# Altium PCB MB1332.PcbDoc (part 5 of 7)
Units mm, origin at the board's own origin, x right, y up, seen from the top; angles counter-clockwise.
Board outline 161 x 75 mm, 6 copper layers (Top Layer, Signal Layer 1, Signal Layer 2, Signal Layer 3, Signal Layer 4, Bottom Layer), stack 1.57 mm thick; 387 components, 358 nets, 1659 pads, 1180 vias.
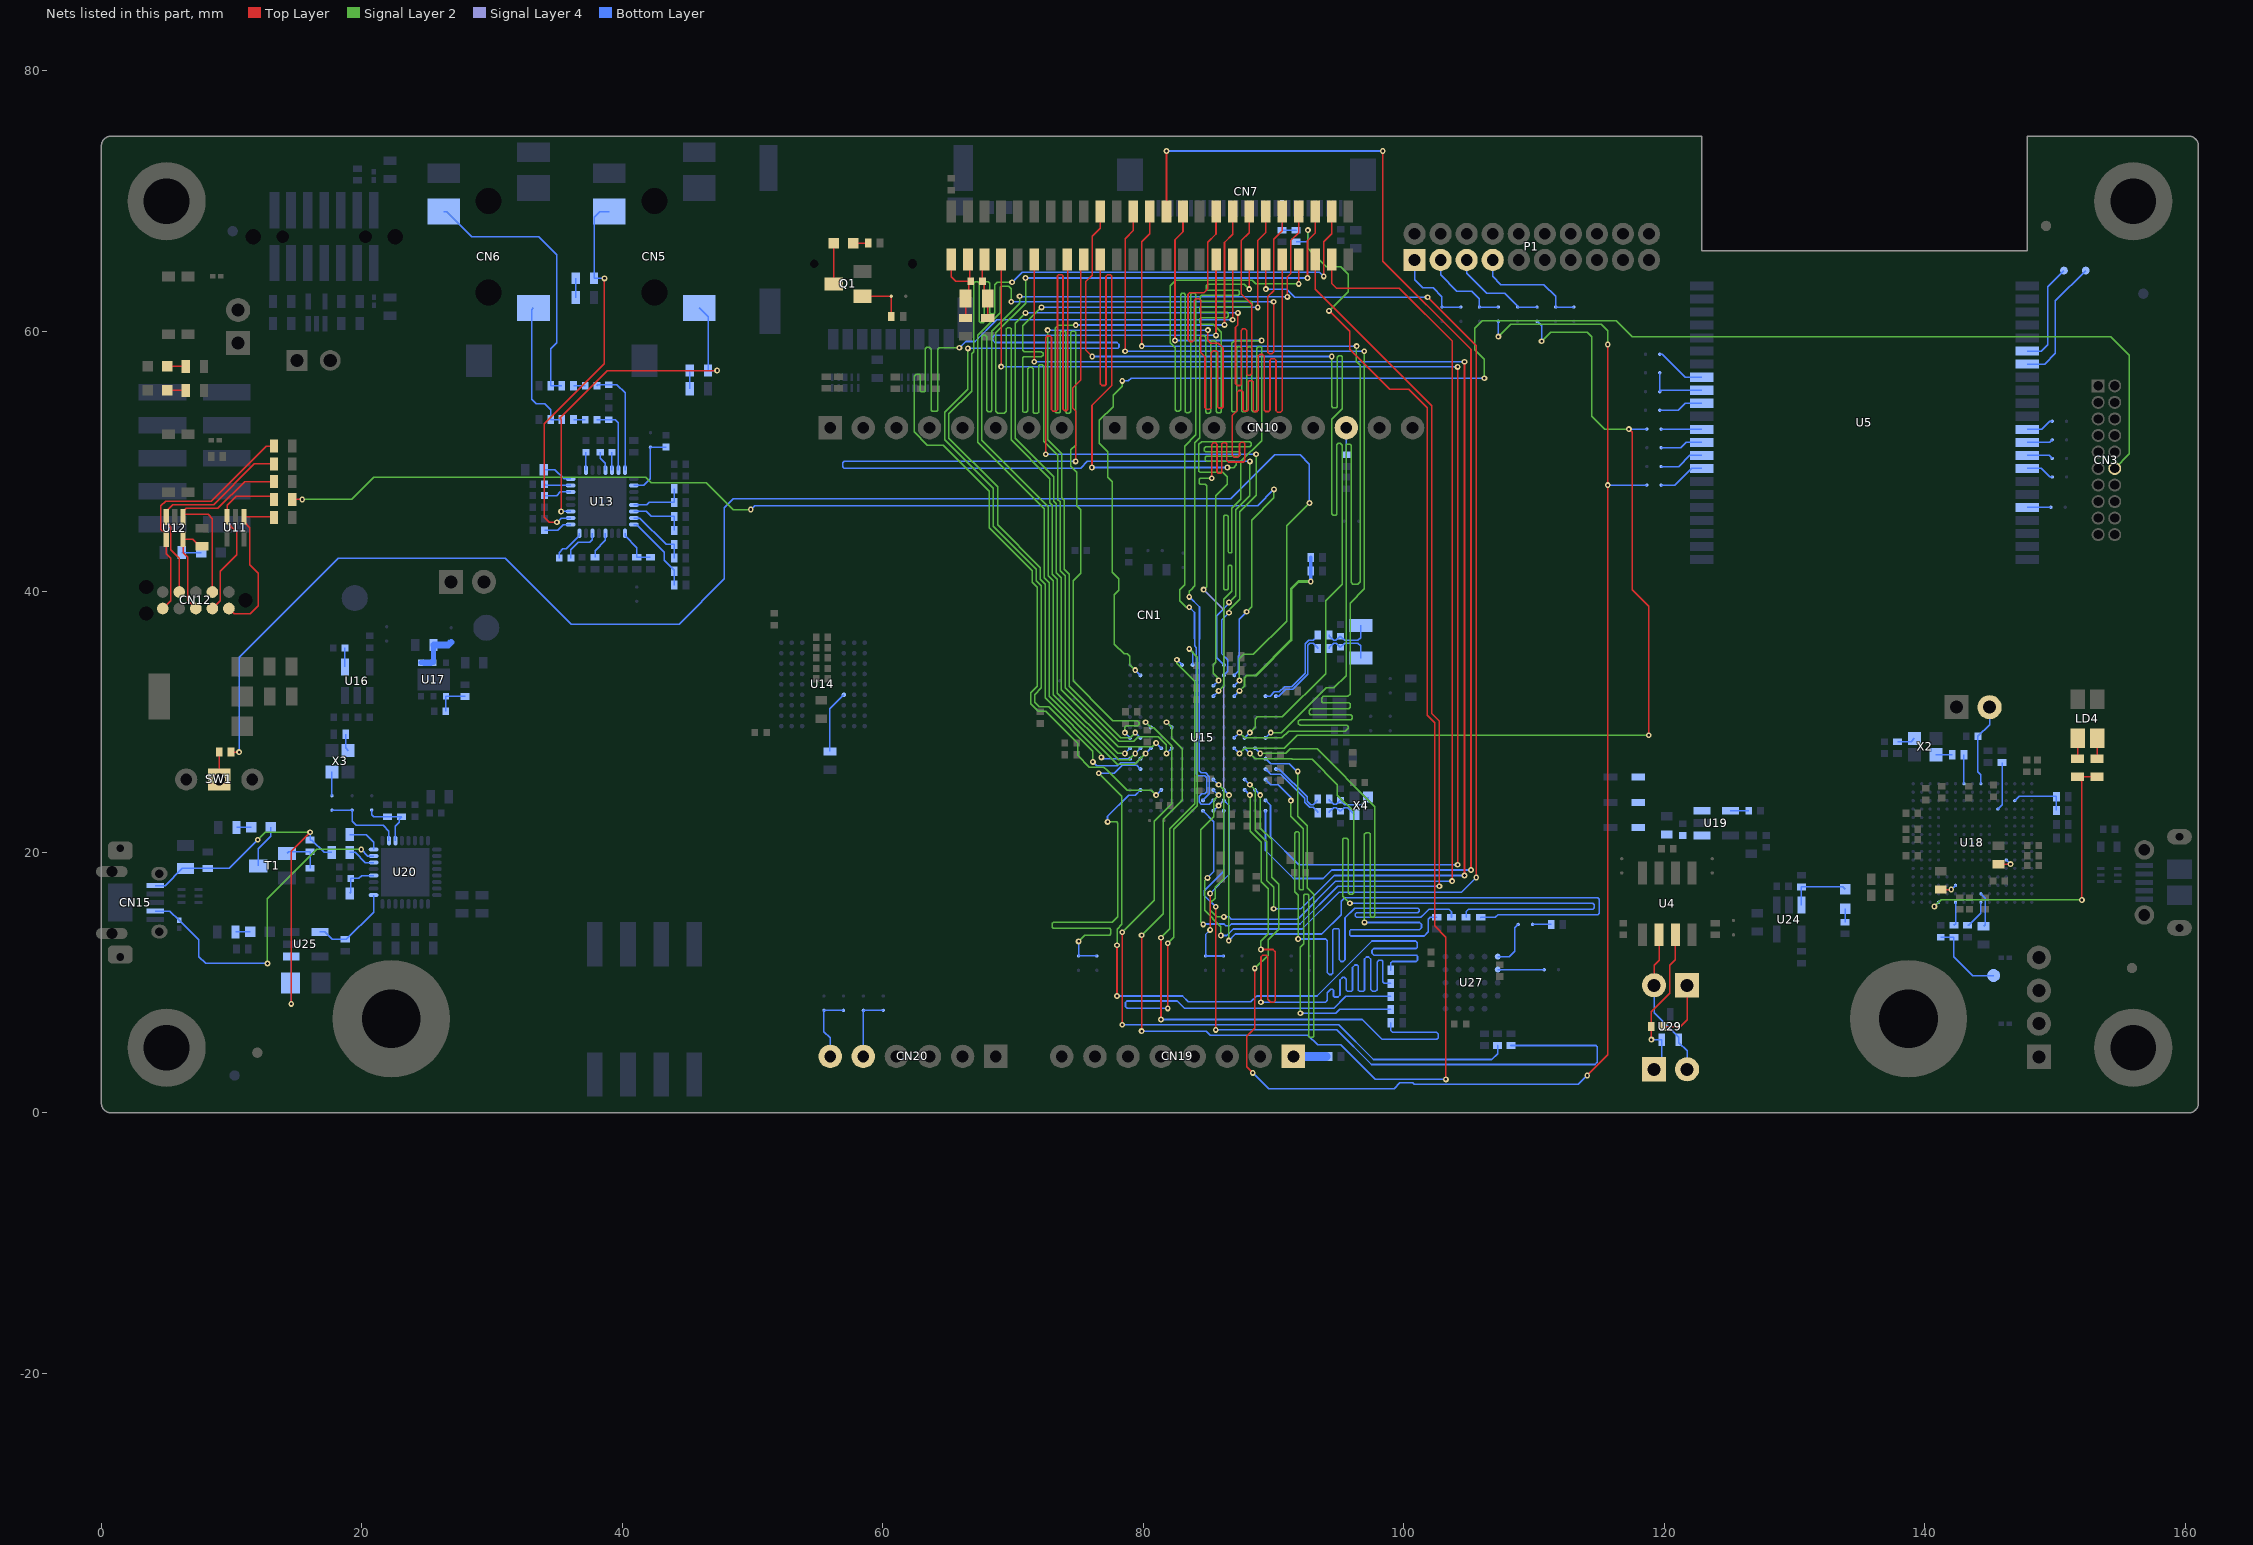
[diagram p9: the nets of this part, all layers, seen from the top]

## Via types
v1: diameter 0.45, hole 0.2, Top Layer to Bottom Layer, tented both sides, 1180 vias

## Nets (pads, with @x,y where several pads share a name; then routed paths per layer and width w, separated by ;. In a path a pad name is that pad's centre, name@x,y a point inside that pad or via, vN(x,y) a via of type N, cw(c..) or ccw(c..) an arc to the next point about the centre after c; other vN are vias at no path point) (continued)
LCD_B5: CN1.31 U15.C7 | length 83.5
  Top Layer w0.127: v1(76.05,49.55) 76.05,54.325 77.579,55.854 77.579,64.246 77.475,64.35 77.25,64.35 77.125,64.225 77.125,55.925 77.05,55.85 76.815,55.85 76.69,55.975 CN1.31@76.69,65.531
  Signal Layer 2 w0.102: v1(85.775,33.198) 85.775,33.348 85.375,33.748 85.375,34.423 85.563,34.611 85.563,47.388 86.45,48.275 86.45,48.825 86.1,49.175 84.357,49.175 84.257,49.275 84.257,51.324 84.482,51.549 88.151,51.549 88.271,51.429 88.271,51.254 88.167,51.15 84.775,51.15 84.675,51.05 84.675,50.85 84.775,50.75 87.375,50.75 87.45,50.675 87.45,50.525 87.325,50.4 84.825,50.4 84.75,50.325 84.75,50.125 84.85,50.025 87,50.025 87.125,49.9 87.125,49.75 86.925,49.55 v1(86.45,49.55)
  Bottom Layer w0.1: U15.C7@85.375,32.798 v1(85.775,33.198)
  Bottom Layer w0.127: v1(76.05,49.55) v1(86.45,49.55)
LCD_B6: CN1.33 U15.A6 | length 82.6
  Top Layer w0.127: v1(74.8,50.025) 74.8,52.152 74.804,52.156 74.804,53.896 74.575,54.125 74.575,55.65 75.2,56.275 75.2,65.312 CN1.33@75.42,65.531
  Signal Layer 2 w0.102: v1(86.575,39.198) 87.094,39.717 87.094,46.296 88.175,47.377 v1(88.175,50.025)
  Bottom Layer w0.127: v1(74.8,50.025) 57.025,50.025 56.925,49.925 56.925,49.6 57.019,49.506 75.181,49.506 75.7,50.025 v1(88.175,50.025) ; U15.A6@86.175,34.398 85.622,34.951 85.622,38.18 86.575,39.133 v1(86.575,39.198)
LCD_B7: CN1.35 U15.B6 | length 83.1
  Top Layer w0.127: v1(72.5,50.575) 72.5,59.55 72.6,59.65 72.85,59.65 72.95,59.55 72.95,54 73.075,53.875 73.275,53.875 73.4,54 73.4,64.25 73.5,64.35 73.725,64.35 73.825,64.25 73.825,54.025 73.925,53.925 74.119,53.925 74.194,54 74.194,65.487 CN1.35@74.15,65.531
  Signal Layer 2 w0.102: v1(86.575,38.398) 86.575,38.623 87.4,39.448 87.4,46.169 88.65,47.419 v1(88.65,50.575)
  Bottom Layer w0.1: U15.B6@86.175,33.598 86.475,33.898 86.475,34.798
  Bottom Layer w0.127: v1(72.5,50.575) v1(88.65,50.575) ; 86.475,34.798 86.003,35.27 86.003,37.826 v1(86.575,38.398)
LCD_BL_CTRL: CN1.43 U15.P2 | length 99.7
  Top Layer w0.127: CN1.43@69.07,65.531 69.075,65.526 v1(69.075,57.3) ; v1(104.125,19.05) v1(104.125,57.275)
  Bottom Layer w0.127: v1(69.075,57.3) 69.094,57.281 104.119,57.281 v1(104.125,57.275) ; U15.P2@89.375,23.998 89.756,23.617 89.756,21.219 91.925,19.05 v1(104.125,19.05)
LCD_CLK: CN1.32 U15.H4 | length 84.1
  Top Layer w0.127: v1(76.075,58.075) 75.581,58.569 75.581,63.83 76.075,64.324 76.075,67.3 76.69,67.915 CN1.32@76.69,69.217
  Signal Layer 2 w0.102: v1(88.175,29.198) 88.575,29.598 88.575,30.223 88.75,30.398 90.675,30.398 94.005,33.728 94.005,39.331 95.251,40.577 95.251,41.754 95.25,41.755 95.25,51.275 95.125,51.4 94.95,51.4 94.85,51.3 94.85,45.975 94.775,45.9 94.575,45.9 94.456,46.019 94.456,53.256 95.25,54.05 95.25,58.075 95.175,58.15 95,58.15 94.875,58.025 94.875,54.225 94.8,54.15 94.556,54.15 94.456,54.25 v1(94.456,58.075)
  Bottom Layer w0.127: v1(76.075,58.075) v1(94.456,58.075) ; U15.H4@87.775,28.798 v1(88.175,29.198)
LCD_DE: CN1.22 U15.D7 | length 89.7
  Top Layer w0.127: v1(82.425,59.3) 82.425,67.05 83.04,67.665 CN1.22@83.04,69.217
  Signal Layer 2 w0.1: 86.175,39.304 86.175,39.45 86.573,39.848
  Signal Layer 2 w0.102: v1(85.775,32.398) 86.175,32.798 86.175,39.304 ; 86.573,39.848 86.788,40.063 86.788,41.987 86.725,42.05 86.575,42.05 86.5,41.975 86.5,40.25 86.425,40.175 86.25,40.175 86.175,40.25 86.175,45.809 86.25,45.885 86.415,45.885 86.5,45.8 86.5,43.075 86.55,43.025 86.75,43.025 86.788,43.063 86.788,46.422 87.475,47.11 87.475,50.025 89.075,51.625 89.075,58.75 89,58.825 88.8,58.825 88.7,58.725 88.7,53.95 88.6,53.85 88.425,53.85 88.325,53.95 88.325,58.725 88.225,58.825 88.05,58.825 87.925,58.7 87.925,53.95 87.825,53.85 87.625,53.85 87.55,53.925 87.55,58.725 87.45,58.825 87.25,58.825 87.175,58.75 87.175,53.925 87.1,53.85 86.875,53.85 86.8,53.925 86.8,59.075 87.025,59.3 v1(89.075,59.3)
  Bottom Layer w0.127: v1(82.425,59.3) v1(89.075,59.3) ; U15.D7@85.375,31.998 v1(85.775,32.398)
LCD_G0: CN1.4 U15.K15 | length 87.5
  Top Layer w0.127: v1(93.85,64.225) 93.85,66.875 94.47,67.495 CN1.4@94.47,69.217
  Signal Layer 2 w0.102: v1(69.925,63.775) 68.775,63.775 68.571,63.571 68.571,61.429 68.517,61.375 68.275,61.375 68.2,61.45 68.2,63.7 68.1,63.8 67.9,63.8 67.8,63.7 67.8,60.775 67.7,60.675 67.5,60.675 67.4,60.775 67.4,63.7 67.3,63.8 67.075,63.8 66.977,63.702 66.977,58.452 66.825,58.3 66.825,55.425 65.069,53.669 65.069,51.806 68.8,48.075 68.8,45.15 72.082,41.868 72.082,40.98 72.467,40.596 72.467,31.858 76.775,27.55 v1(76.775,27.298)
  Bottom Layer w0.1: v1(76.775,27.298) 76.875,27.198 U15.K15@78.975,27.198
  Bottom Layer w0.127: v1(69.925,63.775) 70.7,64.55 93.525,64.55 v1(93.85,64.225)
LCD_G1: CN1.6 U15.J15 | length 83
  Top Layer w0.127: v1(92.6,64.1) 92.6,66.95 93.2,67.55 CN1.6@93.2,69.217
  Signal Layer 2 w0.102: v1(70.95,64.1) 70.95,62.167 68.675,59.892 68.675,53.875 68.825,53.725 69.325,53.725 69.475,53.875 69.475,60.2 69.575,60.3 69.75,60.3 69.843,60.207 69.843,51.676 72.821,48.698 72.821,46.837 73,46.658 73,41.361 73.385,40.976 73.385,32.238 78.025,27.598 v1(78.575,27.598)
  Bottom Layer w0.127: v1(70.95,64.1) v1(92.6,64.1) ; v1(78.575,27.598) U15.J15@78.975,27.998
LCD_G2: CN1.8 U15.J14 | length 82.6
  Top Layer w0.127: v1(91.05,62.65) 91.05,64.175 91.3,64.425 91.3,66.95 91.93,67.58 CN1.8@91.93,69.217
  Signal Layer 2 w0.102: v1(70.5,62.7) 70.5,62.15 68.369,60.019 68.369,53.944 68.275,53.85 68.075,53.85 67.975,53.95 67.975,59.6 67.95,59.625 67.875,59.7 67.708,59.7 67.589,59.581 67.589,51.636 72.694,46.531 72.694,41.234 73.079,40.849 73.079,32.112 78.092,27.098 78.875,27.098 v1(79.375,27.598)
  Bottom Layer w0.127: v1(70.5,62.7) 70.536,62.664 91.036,62.664 v1(91.05,62.65) ; v1(79.375,27.598) U15.J14@79.775,27.998
LCD_G3: CN1.10 U15.J13 | length 82.7
  Top Layer w0.127: v1(90,62.275) 90,58.414 89.861,58.275 89.675,58.275 89.55,58.4 89.55,62.675 90,63.125 90,67.075 90.66,67.735 CN1.10@90.66,69.217
  Signal Layer 2 w0.102: v1(69.85,62.275) 69.85,63.275 69.656,63.469 69.075,63.469 69,63.394 69,61.425 67.283,59.708 67.283,51.509 72.388,46.404 72.388,41.107 72.773,40.722 72.773,31.985 77.984,26.773 79.35,26.773 v1(80.175,27.598)
  Bottom Layer w0.127: v1(69.85,62.275) v1(90,62.275) ; v1(80.175,27.598) U15.J13@80.575,27.998
LCD_G4: CN1.12 U15.J11 | length 84.2
  Top Layer w0.127: v1(88.775,61.85) 88.775,66.975 89.39,67.59 CN1.12@89.39,69.217
  Signal Layer 2 w0.102: v1(72.175,61.85) 70.75,60.425 70.75,58.55 70.85,58.45 72.175,58.45 72.3,58.325 72.3,58.175 72.176,58.051 70.826,58.051 70.75,57.975 70.75,53.85 70.8,53.8 71.025,53.8 71.125,53.9 71.125,57.15 71.225,57.25 71.425,57.25 71.525,57.15 71.525,53.8 71.625,53.7 71.85,53.7 71.95,53.8 71.95,57.375 72.025,57.45 72.225,57.45 72.344,57.331 72.344,51.573 73.433,50.484 73.433,47.09 73.612,46.911 73.612,41.614 73.997,41.229 73.997,32.644 78.092,28.548 79.257,28.548 79.606,28.898 81.127,28.898 81.768,28.257 81.768,27.605 v1(81.775,27.598)
  Bottom Layer w0.127: v1(72.175,61.85) v1(88.775,61.85) ; v1(81.775,27.598) U15.J11@82.175,27.998
LCD_G5: CN1.14 U15.J12 | length 84.4
  Top Layer w0.127: v1@87.25,61.4 87.25,60.5 87.075,60.325 87.075,55.975 87.2,55.85 87.436,55.85 87.525,55.939 87.525,60.1 87.625,60.2 87.8,60.2 87.925,60.075 87.925,56.725 88.025,56.625 88.211,56.625 88.325,56.739 88.325,62.075 87.5,62.9 87.5,66.95 88.12,67.57 CN1.14@88.12,69.217
  Signal Layer 2 w0.102: v1(70.95,61.425) 70.149,60.624 70.149,51.803 73.127,48.825 73.127,46.964 73.306,46.784 73.306,41.487 73.691,41.103 73.691,32.482 78.075,28.098 80.675,28.098 v1(80.975,28.398)
  Bottom Layer w0.127: v1(70.95,61.425) v1(87.25,61.425) ; v1(80.975,28.398) U15.J12@81.375,27.998
LCD_G6: CN1.16 U15.H15 | length 84.9
  Top Layer w0.127: v1(86.225,60.5) 86.225,66.825 86.85,67.45 CN1.16@86.85,69.217
  Signal Layer 2 w0.1: 77.225,30.55 77.65,30.125 79.525,30.125 79.675,29.975 79.675,29.825 79.575,29.725 78.675,29.725 78.575,29.625 v1(78.575,29.198)
  Signal Layer 2 w0.102: v1(74.808,60.488) 74.8,60.481 74.8,60.475 73.475,60.475 73.225,60.225 73.225,53.85 73.325,53.75 73.525,53.75 73.625,53.85 73.625,59.95 73.7,60.025 73.95,60.025 74.025,59.95 74.025,53.825 74.125,53.725 74.3,53.725 74.425,53.85 74.425,59.925 74.525,60.025 74.7,60.025 74.8,59.925 74.8,51.275 74.422,50.897 74.422,49.653 74.9,49.175 74.9,46.6 75.2,46.3 75.2,41.433 74.609,40.842 74.609,33.164 77.224,30.549
  Bottom Layer w0.127: v1(74.808,60.488) 86.213,60.488 v1(86.225,60.5) ; v1(78.575,29.198) U15.H15@78.975,28.798
LCD_G7: CN1.18 U15.H14 | length 88.5
  Top Layer w0.127: v1(84.95,60.1) 84.95,59.313 85.162,59.1 85.75,59.1 86.107,58.743 86.107,54.2 86.031,54.125 85.775,54.125 85.7,54.2 85.7,58.4 85.575,58.525 85.35,58.525 85.2,58.375 85.2,54.15 85.075,54.025 84.85,54.025 84.731,54.144 84.731,58.058 84.4,58.389 84.4,62.375 84.275,62.5 84.025,62.5 83.9,62.375 83.9,59.35 83.775,59.225 83.564,59.225 83.421,59.368 83.421,62.85 83.546,62.975 84.65,62.975 84.95,63.275 84.95,66.85 85.58,67.48 CN1.18@85.58,69.217
  Signal Layer 2 w0.102: v1(72.65,60.1) 72.65,51.7 73.739,50.611 73.739,47.217 73.918,47.038 73.918,41.741 74.303,41.356 74.303,32.77 78.251,28.822 78.999,28.822 v1(79.375,29.198)
  Bottom Layer w0.127: v1(72.65,60.1) v1(84.95,60.1) ; v1(79.375,29.198) U15.H14@79.775,28.798
LCD_HSYNC: CN1.26 U15.H2 | length 83
  Top Layer w0.127: v1(79.875,58.875) 79.875,66.875 80.5,67.5 CN1.26@80.5,69.217
  Signal Layer 2 w0.102: v1(89.775,29.198) 90.6,29.198 94.05,32.648 94.625,32.648 95.557,33.58 95.557,41.882 95.556,41.883 95.556,51.281 95.625,51.35 95.85,51.35 95.95,51.25 95.95,40.725 96.075,40.6 96.45,40.6 96.65,40.8 96.65,57.4 96.35,57.7 96.35,58.85 v1(96.375,58.875)
  Bottom Layer w0.127: v1(79.875,58.875) v1(96.375,58.875) ; U15.H2@89.375,28.798 v1(89.775,29.198)
LCD_INT: CN1.39 U15.M4 | length 106.9
  Top Layer w0.127: CN1.39@71.61,65.531 71.625,65.516 v1(71.625,57.675) ; v1(104.65,18.225) v1(104.65,57.675)
  Signal Layer 2 w0.127: v1(88.175,25.198) 88.586,24.787 88.586,21.712 89.475,20.823 89.475,17.85 90,17.325 v1(90,15.675)
  Bottom Layer w0.127: v1(71.625,57.675) 71.631,57.681 71.637,57.675 v1(104.65,57.675) ; U15.M4@87.775,25.598 v1(88.175,25.198) ; v1(90,15.675) 92.1,15.675 94.65,18.225 v1(104.65,18.225)
LCD_ON/OFF: CN1.24 U15.R2 | length 99.2
  Top Layer w0.127: CN1.24@81.77,69.217 81.775,69.222 v1(81.775,73.85) ; v1(98.375,73.85) 98.375,65.4 105.15,58.625 v1(105.15,18.65)
  Bottom Layer w0.127: v1(81.775,73.85) v1(98.375,73.85) ; U15.R2@89.375,23.198 89.375,20.15 91.525,18 93.8,18 94.45,18.65 v1(105.15,18.65)
LCD_R0: CN1.3 U15.M7 | length 85.3
  Top Layer w0.127: CN1.3@94.47,65.531 94.47,63.68 94.825,63.325 99.65,63.325 103.7,59.275 v1(103.7,17.8) v1@103.7,17.725
  Signal Layer 2 w0.1: 86.175,20.623 86.175,24.015
  Signal Layer 2 w0.102: v1(85.775,25.198) 86.175,24.798 86.175,24.015 ; v1(86.175,15.05) 85.65,15.05 85.15,15.55 85.15,16.125 85.525,16.5 85.525,17.325 86.175,17.975 86.175,20.623
  Bottom Layer w0.127: U15.M7@85.375,25.598 v1(85.775,25.198) ; v1(86.175,15.05) 86.575,15.05 86.743,14.882 91.857,14.882 94.775,17.8 v1(103.7,17.8)
LCD_R1: CN1.5 U15.N7 | length 83.2
  Top Layer w0.127: CN1.5@93.2,65.531 93.2,63.25 102.151,54.299 ; 101.8,54.65 102.151,54.299 ; v1(102.725,17.4) 102.725,30.095 102.151,30.669 102.151,54.299
  Signal Layer 2 w0.102: v1(84.6,14.473) 84.398,14.675 84.398,21.74 85.399,22.741 85.399,24.022 v1(85.775,24.398)
  Bottom Layer w0.127: v1(84.6,14.473) 84.628,14.501 86.186,14.501 86.317,14.369 86.616,14.369 86.748,14.501 92.026,14.501 94.925,17.4 v1(102.725,17.4) ; U15.N7@85.375,24.798 v1(85.775,24.398)
LCD_R2: CN1.7 U15.P7 | length 92.9
  Top Layer w0.127: v1(91.925,63.65) CN1.7@91.93,65.531
  Signal Layer 2 w0.1: 83.177,40.983 83.177,40.551 82.795,40.169 82.795,39.328 83.3,38.823
  Signal Layer 2 w0.102: 83.177,40.983 83.177,51.202 84.025,52.05 84.025,62.85 83.925,62.95 83.725,62.95 83.625,62.85 83.625,53.875 83.5,53.75 83.325,53.75 83.225,53.85 83.225,62.825 83.125,62.925 82.95,62.925 82.85,62.825 82.85,54 82.725,53.875 82.55,53.875 82.436,53.989 82.436,58.757 82.049,59.144 82.049,63.499 82.475,63.925 88.35,63.925 88.625,63.65 v1(91.925,63.65) ; 83.3,38.823 v1(83.525,38.823)
  Bottom Layer w0.1: 83.925,36.402 83.925,35.873 84.075,35.723 84.075,26.048 84.225,25.898 84.699,25.898 84.875,25.723 84.875,24.674 84.699,24.498 84.475,24.498 84.275,24.298 84.275,23.874 84.451,23.698 85.075,23.698 U15.P7@85.375,23.998
  Bottom Layer w0.127: v1(83.525,38.823) 83.925,38.423 83.925,36.402
LCD_R3: CN1.9 U15.R7 | length 85
  Top Layer w0.127: v1(85.25,48.725) 85.25,51.325 85.375,51.45 85.55,51.45 85.65,51.35 85.65,49.2 85.75,49.1 85.95,49.1 86.025,49.175 86.025,51.375 86.112,51.463 86.312,51.463 86.4,51.375 86.4,50.1 86.525,49.975 87.7,49.975 87.775,50.05 87.775,51.4 87.675,51.5 87.5,51.5 87.375,51.375 87.375,50.475 87.25,50.35 86.975,50.35 86.825,50.5 86.825,53.55 87.2,53.925 87.2,55.35 87.319,55.469 87.531,55.469 87.65,55.35 87.65,53.975 87.75,53.875 87.95,53.875 88.05,53.975 88.05,56.125 88.137,56.212 88.337,56.212 88.425,56.125 88.425,53.925 88.5,53.85 88.725,53.85 88.825,53.95 88.825,58.125 88.925,58.225 89.15,58.225 89.275,58.1 89.275,53.95 89.375,53.85 89.625,53.85 89.725,53.95 89.725,57.8 89.819,57.894 90.019,57.894 90.05,57.925 90.175,57.8 90.175,53.925 90.3,53.8 90.525,53.8 90.66,53.935 CN1.9@90.66,65.531
  Signal Layer 2 w0.102: v1(84.625,40.173) 84.85,40.398 84.85,48.15 84.75,48.25 84.375,48.25 84.3,48.325 84.3,48.65 84.375,48.725 v1(85.25,48.725)
  Signal Layer 4 w0.1: v1(84.625,40.173) 86.175,38.623 86.175,23.998 v1(85.775,23.598)
  Bottom Layer w0.1: U15.R7@85.375,23.198 v1(85.775,23.598)
LCD_R4: CN1.11 U15.R8 | length 93.2
  Top Layer w0.127: CN1.11@89.39,65.531 89.4,65.521 v1(89.4,63.25) ; v1(101.825,62.625) 105.55,58.9 v1(105.55,18.075)
  Signal Layer 2 w0.102: v1(84.925,18.05) 84.704,17.829 84.704,15.546 85.95,14.3 v1(85.95,13.625)
  Bottom Layer w0.127: U15.R8@84.575,23.198 85.411,22.362 85.411,18.536 v1(84.925,18.05) ; v1(85.95,13.625) 86.411,13.625 86.906,14.12 92.183,14.12 95.014,16.95 104.425,16.95 v1(105.55,18.075) ; v1(89.4,63.25) 91,63.25 91.625,62.625 v1(101.825,62.625)
LCD_R5: CN1.13 U15.P8 | length 89.1
  Top Layer w0.127: v1(88.13,63.25) CN1.13@88.13,65.521
  Signal Layer 2 w0.102: v1(83.525,39.623) 83.525,40.036 83.7,40.212 83.702,40.212 83.881,40.391 83.881,40.394 83.951,40.464 83.951,51.451 84.331,51.831 84.331,59.525 84.456,59.65 84.675,59.65 84.775,59.55 84.775,53.825 84.875,53.725 85.075,53.725 85.175,53.825 85.175,59.2 85.25,59.275 85.475,59.275 85.575,59.175 85.575,53.875 85.675,53.775 85.9,53.775 85.975,53.85 85.975,59.925 85.35,60.55 84.481,60.55 84.331,60.7 84.331,60.95 84.431,61.05 86.4,61.05 86.525,61.175 86.525,61.375 86.425,61.475 84.406,61.475 84.331,61.55 84.331,61.8 84.431,61.9 88.225,61.9 88.35,62.025 88.35,62.2 88.225,62.325 84.475,62.325 84.35,62.45 84.35,62.65 84.475,62.775 87.275,62.775 87.35,62.85 87.35,63.1 87.275,63.175 84.925,63.175 84.825,63.275 84.825,63.5 84.944,63.619 87.761,63.619 v1(88.13,63.25)
  Bottom Layer w0.1: 84.275,36.354 84.275,26.274 84.451,26.098 84.782,26.098 85.075,25.805 85.075,24.498 U15.P8@84.575,23.998
  Bottom Layer w0.127: v1(83.525,39.623) 84.306,38.842 84.306,36.365 84.285,36.344
LCD_R6: CN1.15 U15.N12 | length 87.8
  Top Layer w0.127: v1(86.85,60.9) CN1.15@86.85,65.531
  Signal Layer 2 w0.1: 77.225,26.3 78.75,24.775 80.598,24.775 v1(80.975,24.398)
  Signal Layer 2 w0.102: v1(65.875,58.75) 64.325,58.75 64.2,58.625 64.2,53.95 64.125,53.875 63.8,53.875 63.725,53.95 63.725,58.625 63.55,58.8 63.375,58.8 63.25,58.675 63.25,55.45 63.175,55.375 62.95,55.375 62.875,55.45 62.875,56.625 62.775,56.725 62.55,56.725 62.4,56.575 62.4,52.294 63.419,51.275 64.616,51.275 68.15,47.741 68.15,44.935 71.47,41.614 71.47,40.727 71.855,40.342 71.855,32.761 71.344,32.25 71.344,31.397 71.916,30.825 72.5,30.825 74.95,28.375 74.95,27.45 75.85,26.55 76.975,26.55 77.225,26.3
  Bottom Layer w0.127: v1(65.875,58.75) 66.35,59.225 67.075,59.225 68.75,60.9 v1(86.85,60.9) ; v1(80.975,24.398) U15.N12@81.375,24.798
LCD_R7: CN1.17 U15.K14 | length 87
  Top Layer w0.127: v1(85.575,59.7) 85.575,65.527 CN1.17@85.58,65.531
  Signal Layer 2 w0.102: v1(66.525,58.7) 66.519,58.694 66.519,55.552 64.763,53.796 64.763,51.679 68.475,47.967 68.475,45.042 71.776,41.741 71.776,40.854 72.161,40.469 72.161,32.634 71.65,32.123 71.65,31.523 72,31.173 72.719,31.173 76.125,27.767 v1(76.125,26.948)
  Bottom Layer w0.1: 78.25,26.898 79.475,26.898 U15.K14@79.775,27.198
  Bottom Layer w0.127: v1(66.525,58.7) 78.05,58.7 78.125,58.775 78.125,59 77.975,59.15 68.6,59.15 68.4,59.35 68.4,59.525 68.575,59.7 v1(85.575,59.7) ; v1(76.125,26.948) 76.425,26.648 78,26.648 78.25,26.898
LCD_VSYNC: CN1.28 U15.H5 | length 86.1
  Top Layer w0.127: v1(78.6,58.475) 78.6,67.125 79.23,67.755 CN1.28@79.23,69.217
  Signal Layer 2 w0.1: 91.142,29.309 91.925,29.309 ; 91.904,30.071 91.904,29.896 92.025,29.775
  Signal Layer 2 w0.102: v1(87.375,29.198) 87.775,28.798 90.631,28.798 91.142,29.309 ; 91.904,30.071 91.905,30.071 92.025,30.191 95.941,30.191 96.05,30.3 96.05,30.45 95.925,30.575 92.825,30.575 92.725,30.675 92.725,30.891 92.859,31.025 95.75,31.025 95.875,31.15 95.875,31.4 95.775,31.5 93.775,31.5 93.7,31.575 93.7,31.85 93.825,31.975 95.7,31.975 95.875,32.15 95.875,39.15 96.956,40.231 v1(96.956,58.475) ; 91.925,29.309 95.509,29.309 95.725,29.525 95.725,29.675 95.625,29.775 92.025,29.775
  Bottom Layer w0.127: v1(78.6,58.475) v1(96.956,58.475) ; U15.H5@86.975,28.798 v1(87.375,29.198)
LED_STLK: R16.2 R17.2 U18.D15 | length 23.1
  Top Layer w0.1: v1(152.05,16.35) 152.05,25.475 R16.2@151.725,25.8 R17.2@153.225,25.8
  Signal Layer 2 w0.1: v1(140.725,15.85) 141.25,16.375 141.275,16.35 v1(152.05,16.35)
  Bottom Layer w0.1: v1(140.725,15.85) U18.D15@141.05,16.175
MCO: C122.2 R99.2 TP3.1 | length 6.2
  Bottom Layer w0.1: C122.2@141.225,13.5 R99.2@142.225,13.5 142.225,12 143.675,10.55 TP3.1@145.275,10.55
MCO1: R25.1 U15.G11 | length 125
  Top Layer w0.1: v1(79.865,6.285) v1(79.865,13.64) ; v1(94.25,61.575) 95.825,60 95.825,58.65 98.9,55.575 100.355,55.575 101.783,54.147 101.783,30.517 102.35,29.95 102.35,14.375 103.225,13.5 v1(103.225,2.575)
  Signal Layer 2 w0.1: v1(79.865,13.64) 81.51,15.285 81.51,22.55 82.975,24.015 82.975,27.948 82.175,28.748 82.175,29.598 v1(81.775,29.998) ; v1(92.625,67.775) 92.625,66.375 94.045,64.955 95.17,64.955 95.731,64.394 95.731,63.031 94.275,61.575 v1(94.25,61.575)
  Bottom Layer w0.1: v1(79.865,6.285) 84.815,6.285 85.125,5.975 92.625,5.975 93.375,5.225 95.167,5.225 97.817,2.575 v1(103.225,2.575) ; v1(81.775,29.998) U15.G11@82.175,29.598 ; R25.1@91.725,66.875 92.525,66.875 92.625,66.975 v1(92.625,67.775)
MEMS_LED: CN3.12 U15.B14 | length 117.8
  Signal Layer 2 w0.1: v1(78.375,56.2) 78.375,55.784 77.675,55.084 77.675,54.234 76.625,53.184 76.625,51.4 77.275,50.75 77.275,48.8 77.625,48.45 77.625,41.5 78.1,41.025 78.1,40.125 77.775,39.8 77.775,35.992 78.517,35.25 78.75,35.25 78.95,35.05 78.95,34.954 78.95,34.423 v1(79.375,33.998) ; v1(106.175,56.4) 106.175,57.85 105.45,58.575 105.45,60.25 106.025,60.825 116.3,60.825 117.52,59.605 154.27,59.605 155.7,58.175 155.7,50.6 CN3.12@154.575,49.475
  Bottom Layer w0.1: v1(78.375,56.2) 78.85,56.2 79.05,56.4 v1(106.175,56.4) ; v1(79.375,33.998) U15.B14@79.775,33.598
MISO: SB10.1 SB19.1 U15.J5 | length 73.4
  Top Layer w0.1: v1(117.275,52.5) 117.525,52.25 117.525,40.175 118.798,38.902 v1(118.798,28.998)
  Signal Layer 2 w0.1: v1(87.375,27.598) 87.775,27.998 90.823,27.998 91.829,29.004 92.95,29.004 92.955,28.998 v1(118.798,28.998) ; v1(110.575,59.25) 111.275,59.95 114.075,59.95 114.425,59.6 114.425,53.5 115.425,52.5 v1(117.275,52.5)
  Bottom Layer w0.1: U15.J5@86.975,27.998 v1(87.375,27.598) ; SB10.1@110.225,60.775 110.575,60.425 v1(110.575,59.25) ; v1(117.275,52.5) SB19.1@118.65,52.5
MOSI: SB8.1 SB26.1 U15.N3 | length 121.4
  Top Layer w0.1: v1(88.4,3.075) 87.93,3.545 87.93,5.88 88.55,6.5 v1(88.55,11.1) ; v1(114.075,2.875) 115.65,4.45 v1(115.65,48.2) v1(115.65,59)
  Signal Layer 2 w0.1: v1(88.55,11.1) 89.575,12.125 89.575,13.294 90.4,14.119 90.4,17.55 89.843,18.107 89.843,21.006 88.975,21.873 v1(88.975,24.398) ; v1(107.25,59.6) 108.2,60.55 115.15,60.55 115.65,60.05 v1(115.65,59)
  Bottom Layer w0.1: v1(88.4,3.075) 89.625,1.85 99.25,1.85 99.7,2.3 100.695,2.3 100.795,2.2 113.4,2.2 v1(114.075,2.875) ; U15.N3@88.575,24.798 v1(88.975,24.398) ; v1(107.25,59.6) SB8.1@107.25,60.775 ; v1(115.65,48.2) SB26.1@118.65,48.2
NetC2_1: C2.1 C3.2 CN1.45 R3.2 | length 4.8
  Top Layer w0.1: CN1.45@67.8,65.531 67.625,65.357 67.625,63.875 C2.1@67.65,63.85 67.775,63.725 67.775,62.8 C3.2@68.05,62.525 R3.2@68.05,61.025
NetC2_2: C2.2 C3.1 CN1.47 CN1.49 R2.2 | length 7.7
  Top Layer w0.1: CN1.49@65.26,65.531 65.26,64.19 65.6,63.85 C2.2@66.75,63.85 ; R2.2@66.35,61.025 C3.1@66.35,62.525 66.6,62.775 66.6,63.7 C2.2@66.75,63.85 ; CN1.47@66.53,65.531 66.675,65.386 66.675,63.925 C2.2@66.75,63.85
NetC44_2: C44.2 U18.M10 | length 1.4
  Top Layer w0.1: C44.2@145.65,19.1 v1(146.575,19.1)
  Bottom Layer w0.1: U18.M10@146.25,19.425 v1(146.575,19.1)
NetC50_2: C50.2 U18.F13 | length 1.3
  Top Layer w0.1: C50.2@141.225,17.15 v1(142.025,17.15)
  Bottom Layer w0.1: v1(142.025,17.15) U18.F13@142.35,17.475
NetC65_1: C65.1 CN5.4 U13.10 | length 29.4
  Top Layer w0.1: v1(34.975,45.35) 34.4,45.35 34,45.75 34,52.9 38.625,57.525 v1(38.625,64.075)
  Bottom Layer w0.1: v1(34.975,45.35) 35.3,45.675 U13.10@36.025,45.675 ; v1(38.625,64.075) C65.1@37.825,64.075 37.825,68.775 38.25,69.2 CN5.4@39,69.2
NetC65_2: C65.2 R27.2 | length 1.5
  Bottom Layer w0.1: R27.2@36.425,62.6 C65.2@36.425,64.075
NetC67_1: C67.1 R35.2 | length 1.4
  Bottom Layer w0.1: R35.2@45.175,55.6 C67.1@45.175,57
NetC67_2: C67.2 CN5.6 U13.11 | length 27.5
  Top Layer w0.1: v1(35.3,46.175) 35.3,53.25 35.2,53.35 38.85,57 v1(47.275,57)
  Bottom Layer w0.1: v1(35.3,46.175) 35.2,46.175 U13.11@36.025,46.175 ; CN5.6@45.9,61.8 46.575,61.125 C67.2@46.575,57 v1(47.275,57)
NetC68_1: C68.1 C69.2 U13.24 | length 8.4
  Bottom Layer w0.1: C69.2@38.05,55.825 38.125,55.9 C68.1@38.95,55.9 39.575,55.9 40.2,55.275 U13.24@40.2,49.35
NetC69_1: C69.1 R33.2 | length 0.9
  Bottom Layer w0.1: R33.2@36.25,55.825 C69.1@37.15,55.825
NetC70_2: C70.2 C71.2 U13.23 | length 5.4
  Bottom Layer w0.1: C71.2@38.05,53.225 C70.2@38.95,53.225 39.45,53.225 39.7,52.975 U13.23@39.7,49.35
NetC71_1: C71.1 R42.2 | length 0.9
  Bottom Layer w0.1: R42.2@36.25,53.225 C71.1@37.15,53.225
NetC72_1: C72.1 SB20.2 U13.26 | length 5.1
  Bottom Layer w0.1: U13.26@40.875,48.175 41.65,48.175 42.15,48.675 SB20.2@42.15,51.125 C72.1@43.35,51.125
NetC73_2: C73.2 U13.22 | length 1.4
  Bottom Layer w0.1: U13.22@39.2,49.35 C73.2@39.2,50.725
NetC74_2: C74.2 U13.21 | length 1.5
  Bottom Layer w0.1: C74.2@38.3,50.725 38.3,50.275 38.7,49.875 U13.21@38.7,49.35
NetC75_1: C75.1 U13.18 | length 1.4
  Bottom Layer w0.1: U13.18@37.2,49.35 C75.1@37.2,50.725
NetC77_2: C77.2 U13.16 | length 2.4
  Bottom Layer w0.1: C77.2@33.95,49.375 34.825,49.375 35.525,48.675 U13.16@36.025,48.675
NetC80_1: C80.1 U13.15 | length 2
  Bottom Layer w0.1: C80.1@34.025,48.275 34.125,48.175 U13.15@36.025,48.175
NetC81_1: C81.1 U13.14 | length 2.1
  Bottom Layer w0.1: C81.1@34.025,47.4 34.95,47.4 35.225,47.675 U13.14@36.025,47.675
NetC84_1: C84.1 U13.9 | length 2.2
  Bottom Layer w0.1: C84.1@34.025,44.725 35.025,44.725 35.475,45.175 U13.9@36.025,45.175
NetC87_1: C87.1 U13.6 | length 3.1
  Bottom Layer w0.1: C87.1@36.05,42.6 36.05,43.25 36.625,43.825 37.5,43.825 37.7,44.025 U13.6@37.7,44.5
NetC87_2: C87.2 U13.8 | length 2.7
  Bottom Layer w0.1: C87.2@35.15,42.6 35.15,43.025 35.425,43.3 35.675,43.3 36.7,44.325 U13.8@36.7,44.5
NetC91_2: C91.2 R62.1 X1.2 | length 3.9
  Bottom Layer w0.1: R62.1@94.275,36.698 94.275,36.598 94.6,36.273 94.775,36.273 95.1,36.598 C91.2@95.125,36.598 95.45,36.273 96.475,36.273 96.675,36.473 X1.2@96.675,37.423
NetC93_2: C93.2 SB33.1 U17.4 U17.5 | length 3.7
  Bottom Layer w0.4: U17.4@24.55,34.575 24.775,34.575 ; 25.275,34.575 U17.5@25.5,34.575 C93.2@25.5,35.925
  Bottom Layer w0.5: 24.775,34.575 25.275,34.575 ; C93.2@25.5,35.925 26.625,35.925 SB33.1@26.85,36.15
NetC94_2: C94.2 U16.4 | length 1.4
  Bottom Layer w0.1: U16.4@18.7,34.25 C94.2@18.7,35.7
NetC95_2: C95.2 R63.1 X1.1 | length 3.9
  Bottom Layer w0.1: R63.1@94.275,35.648 94.275,35.748 94.6,36.073 94.8,36.073 C95.2@95.125,35.748 95.45,36.073 96.475,36.073 96.675,35.873 X1.1@96.675,34.923
NetC100_2: C100.2 R64.2 U17.1 | length 2.6
  Bottom Layer w0.1: C100.2@26.45,30.85 U17.1@26.45,31.975 R64.2@27.925,31.975
NetC104_1: C104.1 CN13.2 U18.J1 | length 6.3
  Bottom Layer w0.1: U18.J1@144.3,25.275 144.3,25.95 144.075,26.175 C104.1@144.075,28.925 144.97,29.82 CN13.2@144.97,31.15
NetC107_2: C107.2 R74.1 X4.3 | length 3.7
  Bottom Layer w0.1: R74.1@94.275,24.098 94.275,24.023 94.6,23.698 94.825,23.698 C107.2@95.125,23.998 95.45,23.673 96.725,23.673 97.25,24.198 X4.3@97.25,24.248
NetC109_2: C109.2 U19.4 | length 1.4
  Bottom Layer w0.1: U19.4@125.075,23.2 C109.2@126.475,23.2
NetC110_2: C110.2 R78.1 X4.1 | length 2.6
  Bottom Layer w0.1: R78.1@94.275,23.048 94.275,23.123 94.6,23.448 94.825,23.448 C110.2@95.125,23.148 95.425,23.448 95.7,23.448 96.2,22.948 X4.1@96.2,22.898
NetC112_2: C112.2 C113.1 D1.2 D2.2 D3.2 U19.1 U19.3
NetC118_1: C118.1 C120.2 U20.20 | length 3
  Bottom Layer w0.1: C120.2@19.075,16.85 19.15,16.925 C118.1@19.15,18 19.775,18 20,18.225 U20.20@20.9,18.225
NetC123_2: C123.2 U18.J14 | length 2.7
  Bottom Layer w0.1: U18.J14@144.3,16.825 144.625,16.5 144.625,14.45 C123.2@144.5,14.325
NetC124_1: C124.1 CN15.1 R83.1 R84.1 R85.2 U21.1 U25.1 | length 33.6
  Top Layer w0.1: v1(14.575,8.375) 14.575,20.1 v1(16.025,21.55)
  Signal Layer 2 w0.1: v1(12,20.975) 12.575,21.55 v1(16.025,21.55)
  Bottom Layer w0.1: CN15.1@4.125,17.45 4.9,17.45 6.225,18.775 R84.1@6.45,18.775 U21.1@8.175,18.775 9.8,18.775 v1(12,20.975) ; v1(14.575,8.375) 14.575,10.025 U25.1@14.575,12 ; v1(16.025,21.55) R83.1@16.025,20.95 16.15,20.95 17.1,20 R85.2@17.675,20
NetCN6_4: CN6.4 R33.1 R34.1 | length 21.1
  Bottom Layer w0.1: CN6.4@26.275,69.2 26.5,69.2 28.45,67.25 33.575,67.25 34.95,65.875 34.95,59.125 34.5,58.675 R34.1@34.5,55.825 R33.1@35.35,55.825
NetCN6_6: CN6.6 R42.1 R43.2 | length 10.5
  Bottom Layer w0.1: CN6.6@33.175,61.8 33.025,61.65 33.025,54.8 33.375,54.45 34.025,54.45 34.5,53.975 R43.2@34.5,53.225 R42.1@35.35,53.225
NetCN7_21: CN7.21 R25.2 R26.2 | length 2.8
  Bottom Layer w0.127: CN7.21@90.654,69.45 90.654,67.779 R26.2@90.65,67.775 R25.2@91.725,67.775
NetCN10_8: CN10.8 R45.1 | length 2.1
  Bottom Layer w0.1: CN10.8@95.584,52.6 95.584,50.541 R45.1@95.6,50.525
NetCN12_2: CN12.2 R40.1 U12.1 | length 16.4
  Top Layer w0.1: U12.1@6.275,45.75 U12.1@6.275,46.025 ; CN12.2@8.52,39.995 8.52,45.63 8.2,45.95 6.35,45.95 U12.1@6.275,46.025 ; R40.1@13.25,48.475 11,48.475 8.95,46.425 6.525,46.425 6.275,46.175 U12.1@6.275,46.025
NetCN12_4: CN12.4 R41.1 U12.3 | length 16.4
  Top Layer w0.1: CN12.4@5.98,39.995 5.98,42.57 5.325,43.225 5.325,44.975 4.975,45.325 U12.3@4.975,45.75 4.975,46.2 5.475,46.7 8.625,46.7 11.75,49.825 R41.1@13.225,49.825
NetCN12_6: CN12.6 R37.1 U12.4 | length 19
  Top Layer w0.1: CN12.6@4.71,38.725 5.325,39.34 5.325,42.575 4.975,42.925 U12.4@4.975,44.05 4.975,44.425 4.575,44.825 4.575,46.6 4.95,46.975 8.425,46.975 12.65,51.2 R37.1@13.2,51.2
NetCN12_8: CN12.8 R36.1 U12.5 | length 7.4
  Top Layer w0.1: CN12.8@7.25,38.725 6.625,39.35 6.625,42.65 6.275,43 U12.5@6.275,44.05 7,44.05 7.55,43.5 R36.1@7.725,43.5
NetCN12_9: CN12.9 R39.1 U11.3 | length 13
  Top Layer w0.1: CN12.9@8.52,38.725 9.125,39.33 9.125,41.575 10.4,42.85 10.4,44.575 9.65,45.325 U11.3@9.65,45.775 9.65,46.65 10.35,47.35 13,47.35 R39.1@13.25,47.1
NetCN12_10: CN12.10 R38.1 U11.1 | length 12.3
  Top Layer w0.1: CN12.10@9.79,38.725 10.19,38.325 11.425,38.325 12.05,38.95 12.05,41.425 11.4,42.075 11.4,44.925 10.95,45.375 U11.1@10.95,45.775 13.2,45.775 R38.1@13.25,45.725
NetCN15_4: CN15.4 U20.23 U26.1 | length 25.9
  Signal Layer 2 w0.1: v1(12.75,11.475) 12.75,16.425 16.55,20.225 v1(19.95,20.225)
  Bottom Layer w0.1: CN15.4@4.125,15.5 5.263,15.5 U26.1@5.975,14.787 7.475,13.287 7.475,12 8,11.475 v1(12.75,11.475) ; v1(19.95,20.225) 20.45,19.725 U20.23@20.9,19.725
NetCN18_1: CN18.1 R21.1 | length 4.7
  Top Layer w0.1: R21.1@119.9,6.625 121.225,6.625 121.745,7.145 CN18.1@121.745,9.8
NetCN18_2: CN18.2 CN21.2 U4.6 U29.1 | length 11.5
  Top Layer w0.1: CN18.2@119.205,9.8 119.205,11.33 119.59,11.715 U4.6@119.59,13.675
  Bottom Layer w0.1: CN18.2@119.205,9.8 119.205,7.695 121.1,5.8 U29.1@121.1,5.625 121.1,5.4 121.745,4.755 CN21.2@121.745,3.35
NetCN19_1: CN19.1 R114.1 | length 2.5
  Bottom Layer w0.7: CN19.1@91.52,4.34 91.535,4.325 R114.1@94.025,4.325
NetCN20_5: CN20.5 SB52.2 SB53.2 | length 5.1
  Bottom Layer w0.1: CN20.5@58.5,4.34 SB53.2@58.5,7.875 SB52.2@60.025,7.875
NetCN20_6: CN20.6 SB54.2 SB55.2 | length 5.2
  Bottom Layer w0.1: CN20.6@55.96,4.34 55.96,5.765 55.475,6.25 SB55.2@55.475,7.875 SB54.2@56.975,7.875
NetCN21_1: CN21.1 R21.2 U4.7 U29.2 | length 12.1
  Top Layer w0.1: v1(119,5.625) R21.2@119,6.625 119,7.775 120.425,9.2 120.425,11.325 120.85,11.75 120.85,13.665 U4.7@120.86,13.675
  Bottom Layer w0.1: v1(119,5.625) U29.2@119.8,5.625 119.8,3.945 CN21.1@119.205,3.35
NetLD1_1: LD1.1 R1.1 | length 1.2
  Top Layer w0.1: LD1.1@57.725,66.775 R1.1@58.875,66.775
NetLD1_2: LD1.2 Q1.3 | length 3.1
  Top Layer w0.1: Q1.3@56.225,63.65 LD1.2@56.225,66.775
NetLD2_2: LD2.2 R4.1 | length 1.4
  Top Layer w0.1: LD2.2@5.05,57.325 R4.1@6.475,57.325
NetLD3_2: LD3.2 R10.1 | length 1.4
  Top Layer w0.1: LD3.2@5.05,55.475 R10.1@6.475,55.475
NetLD4_2: LD4.2 R17.1 | length 1.6
  Top Layer w0.1: R17.1@153.225,27.2 LD4.2@153.225,28.775
NetLD4_3: LD4.3 R16.1 | length 1.6
  Top Layer w0.1: R16.1@151.725,27.2 LD4.3@151.725,28.775
NetLD5_1: LD5.1 R61.2 | length 1.5
  Bottom Layer w0.1: R61.2@6.175,43.025 LD5.1@7.675,43.025
NetLD6_1: LD6.1 R80.1 | length 1.1
  Bottom Layer w0.1: R80.1@10.375,21.925 LD6.1@11.5,21.925
NetLD6_2: LD6.2 T1.3 | length 3.3
  Bottom Layer w0.1: T1.3@12.05,18.975 12.05,20.275 13,21.225 LD6.2@13,21.925
NetLD7_1: LD7.1 R96.1 | length 1
  Bottom Layer w0.1: R96.1@133.875,14.65 LD7.1@133.875,15.675
NetLD7_2: LD7.2 R87.2 U24.3 | length 4.8
  Bottom Layer w0.1: U24.3@130.525,15.95 R87.2@130.525,17.35 133.7,17.35 LD7.2@133.875,17.175
NetLD8_1: LD8.1 R90.1 | length 1.1
  Bottom Layer w0.1: R90.1@10.3,13.9 LD8.1@11.425,13.9
NetP1_1: P1.1 SB6.2 SB7.2 | length 6.4
  Bottom Layer w0.1: P1.1@100.82,65.49 100.82,63.98 101.45,63.35 102.25,63.35 102.925,62.675 SB7.2@102.925,61.875 SB6.2@104.375,61.875
NetP1_2: P1.2 SB8.2 SB9.2 | length 7
  Bottom Layer w0.1: P1.2@102.82,65.49 102.82,64.355 104.075,63.1 105.2,63.1 105.8,62.5 SB9.2@105.8,61.875 SB8.2@107.25,61.875
NetP1_3: P1.3 SB10.2 SB11.2 | length 7.5
  Bottom Layer w0.1: P1.3@104.82,65.49 104.82,64.48 106.375,62.925 107.75,62.925 108.725,61.95 SB11.2@108.725,61.875 SB10.2@110.225,61.875
NetP1_4: P1.4 SB12.2 SB13.2 | length 8.9
  Bottom Layer w0.1: P1.4@106.82,65.49 106.82,64.23 107.45,63.6 110.75,63.6 111.65,62.7 SB13.2@111.65,61.875 SB12.2@113.05,61.875
NetQ1_1: Q1.1 R115.2 SB1.2 | length 3.8
  Top Layer w0.1: Q1.1@58.425,62.7 SB1.2@60.65,62.7 R115.2@60.65,61.15
NetR15_1: R15.1 U15.C5 | length 124
  Top Layer w0.1: R15.1@9.95,27.7 v1(10.575,27.7)
  Signal Layer 2 w0.1: v1(87.375,33.198) 87.375,34.873 87.7,35.198 88.448,35.198 91.011,37.761 91.011,45.086 v1(92.75,46.825)
  Bottom Layer w0.1: v1(10.575,27.7) 10.575,34.975 18.175,42.575 31.025,42.575 36.075,37.525 44.35,37.525 47.825,41 47.825,46.45 48.525,47.15 86.725,47.15 90.1,50.525 92.025,50.525 92.75,49.8 v1(92.75,46.825) ; U15.C5@86.975,32.798 v1(87.375,33.198)
NetR15_2: R15.2 SW1.1 | length 2.1
  Top Layer w0.1: SW1.1@9.05,25.6 R15.2@9.05,27.7
NetR46_1: R46.1 R47.1 U13.29 | length 4.2
  Bottom Layer w0.1: U13.29@40.875,46.675 41.875,46.675 42.075,46.875 R47.1@43.975,46.875 R46.1@43.975,47.925
NetR48_1: R48.1 R49.1 U13.30 | length 4.3
  Bottom Layer w0.1: U13.30@40.875,46.175 41.825,46.175 42.2,45.8 R48.1@43.975,45.8 R49.1@43.975,44.725
NetR50_1: R50.1 R52.1 U13.31 | length 5
  Bottom Layer w0.1: U13.31@40.875,45.675 41.35,45.675 43.375,43.65 R50.1@43.975,43.65 R52.1@43.975,42.6
NetR51_2: R51.2 R58.2 U15.D5 | length 14
  Signal Layer 2 w0.15: v1(87.375,32.398) 87.775,32.798 87.775,33.423 87.95,33.598 88.65,33.598
  Signal Layer 2 w0.2: 88.65,33.598 91.35,36.298 91.35,40.224 91.924,40.798 v1(92.85,40.798)
  Bottom Layer w0.1: U15.D5@86.975,31.998 v1(87.375,32.398)
  Bottom Layer w0.3: v1(92.85,40.798) R58.2@92.85,41.598 R51.2@92.85,42.648
NetR53_1: R53.1 R54.1 U13.1 | length 3.3
  Bottom Layer w0.1: U13.1@40.2,44.5 40.2,44.3 41.1,43.4 R54.1@41.1,42.65 R53.1@42.15,42.65
NetR57_1: R57.1 U13.4 | length 2.2
  Bottom Layer w0.1: R57.1@37.9,42.65 37.9,43.15 38.7,43.95 U13.4@38.7,44.5
NetR59_1: R59.1 R60.1 U13.32 | length 6.1
  Bottom Layer w0.1: U13.32@40.875,45.175 41.1,45.175 43.225,43.05 43.225,42.425 43.979,41.671 R59.1@43.979,41.583 R60.1@43.979,40.523
NetR62_2: R62.2 U15.D2 | length 6.9
  Bottom Layer w0.1: U15.D2@89.375,31.998 89.725,31.998 90.05,32.323 90.442,32.323 90.842,32.723 91.392,32.723 92.425,33.756 92.425,36.006 92.692,36.273 93.05,36.273 R62.2@93.175,36.398
NetR63_2: R63.2 U15.D1 | length 6.4
  Bottom Layer w0.1: U15.D1@90.175,31.998 90.4,31.998 90.925,32.523 91.475,32.523 92.625,33.673 92.625,35.923 92.775,36.073 93.025,36.073 93.375,35.723 R63.2@93.375,35.648
NetR65_2: R65.2 X3.1 | length 1.3
  Bottom Layer w0.1: R65.2@18.75,29.075 18.75,28.025 X3.1@18.95,27.825
NetR66_2: R66.2 X2.1 | length 1.4
  Bottom Layer w0.1: R66.2@137.9,28.5 138.95,28.5 X2.1@139.2,28.75
NetR67_1: R67.1 U14.F3 | length 4.8
  Bottom Layer w0.1: R67.1@55.925,27.75 55.925,31.025 U14.F3@57,32.1
NetR69_2: R69.2 U18.L4 | length 3.7
  Bottom Layer w0.1: U18.L4@145.6,23.325 145.925,23.65 R69.2@145.925,26.9
NetR70_1: R70.1 X2.3 | length 1.3
  Bottom Layer w0.1: X2.3@140.85,27.5 R70.1@142.1,27.5
NetR70_2: R70.2 U18.G1 | length 2.2
  Bottom Layer w0.1: U18.G1@143,25.275 R70.2@143,27.5
NetR73_1: R73.1 R77.1 U18.N3 | length 4.4
  Bottom Layer w0.1: U18.N3@146.9,23.975 147.225,24.3 150.075,24.3 R73.1@150.1,24.275 R77.1@150.1,23.225
NetR74_2: R74.2 U15.L1 | length 4.7
  Bottom Layer w0.1: U15.L1@90.175,26.398 90.433,26.398 92.575,24.256 92.575,23.948 92.85,23.673 93.05,23.673 93.35,23.973 R74.2@93.35,24.023
NetR75_1: R75.1 R76.2 SB40.1 U20.27 | length 4.8
  Bottom Layer w0.1: SB40.1@20.75,23.25 20.75,22.9 20.9,22.75 R76.2@21.975,22.75 R75.1@23.05,22.75 22.85,22.55 22.85,22.3 22.575,22.025 U20.27@22.575,20.9
NetR78_2: R78.2 U15.L2 | length 5.6
  Bottom Layer w0.1: U15.L2@89.375,26.398 89.775,25.998 90.55,25.998 92.375,24.173 92.375,23.865 92.767,23.473 93.025,23.473 93.375,23.123 R78.2@93.375,23.048
NetR81_1: R81.1 U20.24 | length 2.6
  Bottom Layer w0.1: R81.1@19.075,21.375 20.325,21.375 20.9,20.8 U20.24@20.9,20.225
NetR83_2: R83.2 R86.1 T1.1 | length 3.1
  Bottom Layer w0.1: T1.1@14.25,19.925 14.375,20.05 R83.2@16.025,20.05 R86.1@16.025,18.775
NetR85_1: R85.1 U20.22 | length 2.1
  Bottom Layer w0.1: R85.1@19.075,20 19.5,20 20.275,19.225 U20.22@20.9,19.225
NetR91_2: R91.2 U15.N6 | length 52.5
  Signal Layer 2 w0.102: v1(86.55,13.225) 86.551,13.226 86.551,24.374 v1(86.575,24.398)
  Bottom Layer w0.1: U15.N6@86.175,24.798 v1(86.575,24.398)
  Bottom Layer w0.127: v1(86.55,13.225) 87.064,13.739 93.7,13.739 95.187,15.226 95.187,16.262 95.45,16.525 114.875,16.525 115,16.4 115,15.325 114.9,15.225 107.225,15.225 107.025,15.025 R91.2@105.9,15.025 R91.2@105.9,15
NetR92_1: R92.1 U15.J4 | length 56.8
  Signal Layer 2 w0.102: v1(88.175,27.598) 88.573,27.2 91.375,27.2 91.425,27.15 92.95,27.15 94.9,25.2 94.9,24.4 96.139,23.161 96.139,16.889 96.05,16.8 95.825,16.8 95.725,16.9 95.725,20.975 95.6,21.1 95.4,21.1 95.3,21 95.3,16.65 v1(95.85,16.1)
  Bottom Layer w0.1: U15.J4@87.775,27.998 v1(88.175,27.598)
  Bottom Layer w0.127: v1(95.85,16.1) 114.5,16.1 114.619,15.981 114.619,15.744 114.5,15.625 104.95,15.625 104.775,15.45 R92.1@104.775,15.025
NetR93_2: R93.2 U15.M2 | length 58
  Signal Layer 2 w0.1: 91.637,20.623 91.637,20.644 91.636,20.645 91.636,21.475 91.736,21.575 91.875,21.575 91.925,21.525 ; 91.709,22.375 91.925,22.159
  Signal Layer 2 w0.102: v1(91.325,23.973) 91.325,22.759 91.709,22.375 ; 91.637,20.623 91.637,16.963 91.875,16.725 v1(91.875,13.35) ; 91.925,21.525 91.95,21.5 91.95,17.2 92.025,17.125 92.225,17.125 92.264,17.164 92.264,21.82 91.925,22.159
  Bottom Layer w0.1: U15.M2@89.375,25.598 89.775,25.198 90.35,25.198 91.325,24.223 v1(91.325,23.973)
  Bottom Layer w0.127: v1(91.875,13.35) 94,13.35 94.125,13.225 94.125,10.775 94.275,10.625 94.436,10.625 94.544,10.733 94.544,14.044 94.65,14.15 94.95,14.15 95.05,14.05 95.05,11.75 95.175,11.625 95.35,11.625 95.475,11.75 95.475,14.975 96.219,15.719 101.081,15.719 101.175,15.625 101.175,15.475 101.075,15.375 96.375,15.375 96.275,15.275 96.275,15.125 96.375,15.025 101.3,15.025 101.5,15.225 101.9,15.625 103.475,15.625 103.65,15.45 R93.2@103.65,15.025
NetR94_1: R94.1 U15.J3 | length 52.3
  Signal Layer 2 w0.1: 90.925,27.598 91.277,27.95 91.925,27.95
  Signal Layer 2 w0.102: v1(88.975,27.598) 90.925,27.598 ; 91.925,27.95 93.35,27.95 97.775,23.525 97.775,15.125 97.675,15.025 97.5,15.025 97.4,15.125 97.4,21.425 97.3,21.525 97.1,21.525 96.975,21.4 v1(96.975,14.625)
  Bottom Layer w0.1: U15.J3@88.575,27.998 v1(88.975,27.598)
  Bottom Layer w0.127: v1(96.975,14.625) 101.2,14.625 101.35,14.475 101.35,14.225 101.2,14.075 95.931,14.075 95.856,14 95.856,13.65 95.925,13.581 101.556,13.581 101.875,13.9 101.875,14.875 102.025,15.025 R94.1@102.525,15.025
NetR95_1: R95.1 U20.17 U25.4 | length 6.5
  Bottom Layer w0.1: U25.4@16.775,13.9 17.15,13.9 17.725,13.325 R95.1@18.725,13.325 18.8,13.325 20.9,15.425 U20.17@20.9,16.725
NetR97_1: R97.1 SB43.2 | length 1.4
  Bottom Layer w0.1: SB43.2@109.875,14.475 R97.1@111.3,14.475
NetR98_2: R98.2 U18.J15 | length 2.3
  Bottom Layer w0.1: R98.2@143.275,14.4 143.375,14.4 144.3,15.325 U18.J15@144.3,16.175
NetR99_1: R99.1 U18.F15 | length 1.8
  Bottom Layer w0.1: R99.1@142.225,14.4 142.35,14.525 U18.F15@142.35,16.175
NetR106_1: R106.1 U15.L14 | length 57.6
  Top Layer w0.127: v1(77.975,8.975) v1(77.975,12.875)
  Signal Layer 2 w0.1: 77.225,25.425 78.356,24.294 78.356,20.623
  Signal Layer 2 w0.102: v1(76.575,26.075) 77.225,25.425 ; v1(77.975,12.875) 77.975,14.1 78.356,14.481 78.356,20.623
  Bottom Layer w0.1: 77.75,26.075 78.373,26.698 79.475,26.698 U15.L14@79.775,26.398
  Bottom Layer w0.127: v1(76.575,26.075) 77.75,26.075 ; v1(77.975,8.975) 83,8.975 83.45,8.525 88.25,8.525 88.7,8.975 93.325,8.975 97.55,13.2 100.9,13.2 101.025,13.075 101.025,12.7 100.95,12.625 97.675,12.625 97.55,12.5 97.55,12.25 97.7,12.1 100.975,12.1 101.05,12.025 101.05,11.725 100.95,11.625 99.1,11.625 99,11.525 R106.1@99,10.95
NetR107_2: R107.2 U15.N4 | length 52.4
  Top Layer w0.127: v1(89.025,8.5) 89.025,11.975 89.15,12.1 89.45,12.1 89.55,12 89.55,8.725 89.775,8.5 90,8.5 90.125,8.625 90.125,12.375 89.95,12.55 v1(89.025,12.55)
  Signal Layer 2 w0.1: v1(88.175,24.398) 88.201,24.372 88.201,21.624 89.05,20.775
  Signal Layer 2 w0.102: v1(89.025,12.55) 89.025,13.175 89.6,13.75 89.6,17.2 89.05,17.75 89.05,20.775
  Bottom Layer w0.1: U15.N4@87.775,24.798 v1(88.175,24.398)
  Bottom Layer w0.127: v1(89.025,8.5) 93.975,8.5 94.125,8.65 94.125,9.236 94.389,9.5 94.525,9.5 94.6,9.425 94.6,8.975 94.675,8.9 94.947,8.9 95.1,9.053 95.1,10.211 95.314,10.425 95.425,10.425 95.575,10.275 95.575,9.431 95.675,9.331 95.95,9.331 96.05,9.431 96.05,11.161 96.244,11.356 96.419,11.356 96.5,11.275 96.5,9.425 96.594,9.331 96.875,9.331 96.975,9.431 96.975,11.825 97.125,11.975 97.286,11.975 97.45,11.811 97.45,9.475 97.594,9.331 97.825,9.331 97.95,9.456 97.95,11.594 98.075,11.719 98.3,11.719 98.375,11.644 98.375,10.075 98.5,9.95 R107.2@99,9.95
NetR108_2: R108.2 U15.A9 | length 54.8
  Top Layer w0.127: v1(81.875,8.025) v1(81.875,13.025)
  Signal Layer 2 w0.1: 82.342,21.767 84.15,23.575 84.15,34.998 v1(83.525,35.623)
  Signal Layer 2 w0.102: v1(81.875,13.025) 82.342,13.492 82.342,21.767
  Bottom Layer w0.1: v1(83.525,35.623) 83.775,35.373 U15.A9@83.775,34.398
  Bottom Layer w0.127: v1(81.875,8.025) 78.75,8.025 78.625,8.15 78.625,8.475 78.744,8.594 82.606,8.594 83.161,8.039 94.596,8.039 94.61,8.024 95.536,8.95 R108.2@99,8.95
NetR109_1: R109.1 U15.K2 | length 51.7
  Signal Layer 2 w0.102: v1(91.852,26.219) 91.852,22.773 92.57,22.055 92.57,17.305 93.075,16.8 93.075,5.9 93,5.825 92.775,5.825 92.7,5.9 92.7,16.7 92.6,16.8 92.375,16.8 92.3,16.725 92.3,12.975 92.05,12.725 v1(92.05,7.65)
  Bottom Layer w0.1: U15.K2@89.375,27.198 89.775,26.798 91.2,26.798 91.8,26.198 91.832,26.198 v1(91.852,26.219)
  Bottom Layer w0.127: v1@92.05,7.643 94.768,7.643 95.075,7.95 R109.1@99,7.95
NetR110_1: R110.1 U15.A10 | length 56.5
  Top Layer w0.127: v1(81.35,7.175) v1(81.35,13.45)
  Signal Layer 2 w0.1: 82.035,21.81 83.95,23.725 83.95,33.154 82.575,34.529 v1(82.575,34.798)
  Signal Layer 2 w0.102: v1(81.35,13.45) 82.035,14.135 82.035,21.81
  Bottom Layer w0.1: v1(82.575,34.798) U15.A10@82.975,34.398
  Bottom Layer w0.127: v1(81.35,7.175) 96.8,7.175 98.325,5.65 102.525,5.65 102.65,5.775 102.65,6.05 102.5,6.2 99.125,6.2 99,6.325 R110.1@99,6.925
NetR111_2: R111.2 U15.R6 | length 56.1
  Top Layer w0.127: v1(85.55,6.375) v1(85.55,15.825)
  Bottom Layer w0.1: 86.175,20.623 U15.R6@86.175,23.198
  Bottom Layer w0.127: v1(85.55,6.375) 94.85,6.375 97.506,3.719 114.669,3.719 114.85,3.9 114.85,5.075 114.75,5.175 R111.2@108.225,5.175 ; v1(85.55,15.825) 84.675,16.7 84.675,17.05 86.175,18.55 86.175,20.623
NetR112_2: R112.2 U15.G13 | length 57.1
  Top Layer w0.127: v1(78.375,6.775) v1(78.374,13.874)
  Signal Layer 2 w0.102: v1(78.374,13.874) 80.825,16.325 80.825,22.375 82.175,23.725 82.175,28.2 80.802,29.573 80.6,29.573 v1(80.175,29.998)
  Bottom Layer w0.127: v1(78.375,6.775) 94.989,6.775 97.664,4.1 106.75,4.1 107.2,4.55 R112.2@107.2,5.175 ; v1(80.175,29.998) U15.G13@80.575,29.598
NetSB14_1: SB14.1 U5.15 | length 3.9
  Bottom Layer w0.1: SB14.1@119.65,58.25 119.85,58.25 120.35,57.75 121.615,56.485 U5.15@122.861,56.485
NetSB15_1: SB15.1 SB16.1 U5.14 | length 4.7
  Bottom Layer w0.1: SB15.1@119.65,56.825 SB16.1@119.65,55.375 119.76,55.485 U5.14@122.861,55.485
NetSB17_1: SB17.1 U5.13 | length 3.4
  Bottom Layer w0.1: SB17.1@119.65,53.95 121.05,53.95 121.585,54.485 U5.13@122.861,54.485
NetSB18_1: SB18.1 U5.34 | length 2.2
  Bottom Layer w0.1: U5.34@147.861,52.485 148.96,52.485 149.075,52.6 149.575,53.1 SB18.1@149.775,53.1
NetSB19_2: SB19.2 U5.11 | length 3.1
  Bottom Layer w0.1: SB19.2@119.75,52.5 119.765,52.485 U5.11@122.861,52.485
NetSB21_1: SB21.1 U5.35 | length 2
  Bottom Layer w0.1: U5.35@147.861,51.485 149.585,51.485 SB21.1@149.775,51.675
NetSB22_2: SB22.2 U5.10 | length 3.3
  Bottom Layer w0.1: SB22.2@119.75,51.075 121.25,51.075 121.66,51.485 U5.10@122.861,51.485
NetSB23_1: SB23.1 U5.36 | length 2
  Bottom Layer w0.1: U5.36@147.861,50.485 149.54,50.485 SB23.1@149.775,50.25
NetSB24_2: SB24.2 U5.9 | length 3.5
  Bottom Layer w0.1: SB24.2@119.75,49.625 121.1,49.625 121.96,50.485 U5.9@122.861,50.485
NetSB25_1: SB25.1 U5.37 | length 2.2
  Bottom Layer w0.1: U5.37@147.861,49.485 148.915,49.485 149.075,49.325 149.575,48.825 SB25.1@149.775,48.825
NetSB26_2: SB26.2 U5.8 | length 3.6
  Bottom Layer w0.1: SB26.2@119.75,48.2 120.8,48.2 122.085,49.485 U5.8@122.861,49.485
NetSB27_2: SB27.2 U5.40 | length 1.8
  Bottom Layer w0.1: U5.40@147.861,46.485 149.66,46.485 SB27.2@149.675,46.5
NetSB41_1: SB41.1 SB42.1 U20.26 | length 6.3
  Bottom Layer w0.1: SB42.1@17.7,23.25 SB41.1@19.25,23.25 19.25,22.4 19.575,22.075 21.625,22.075 22.075,21.625 U20.26@22.075,20.9
NetSB42_2: SB42.2 X3.3 | length 1.8
  Bottom Layer w0.1: SB42.2@17.7,24.35 X3.3@17.7,26.175
NetSB43_1: SB43.1 U27.A5 | length 3.7
  Bottom Layer w0.1: U27.A5@107.2,12 108.1,12 108.5,12.4 108.5,14.2 SB43.1@108.775,14.475
NetSB47_1: SB47.1 SB50.1 U15.P6 | length 14.2
  Top Layer w0.127: v1(85.125,14.05) v1(85.125,16.85)
  Bottom Layer w0.127: v1(85.125,14.05) 84.775,13.7 SB47.1@84.775,12.05 SB50.1@86.15,12.05 ; v1(85.125,16.85) 86.575,18.3 86.575,23.598 U15.P6@86.175,23.998
NetSB48_1: SB48.1 SB49.1 U15.N14 | length 27.5
  Signal Layer 2 w0.102: v1(75.025,13.175) 75.5,13.65 77.4,13.65 77.5,13.75 77.5,14.075 77.4,14.175 73.075,14.175 73,14.25 73,14.55 73.1,14.65 77.625,14.65 78.05,15.075 78.05,22.25 77.95,22.35 v1(77.25,22.35)
  Bottom Layer w0.1: SB49.1@75.025,12.05 SB48.1@76.425,12.05
  Bottom Layer w0.127: SB49.1@75.025,12.05 v1(75.025,13.175) ; v1(77.25,22.35) 77.25,22.775 78.875,24.4 79.377,24.4 U15.N14@79.775,24.798
NetSB51_2: SB51.2 U27.A4 | length 3.6
  Bottom Layer w0.1: U27.A4@107.2,11 SB51.2@110.775,11
NetTP4_1: TP4.1 U5.29 | length 9.8
  Bottom Layer w0.1: U5.29@147.861,57.485 149.185,57.485 150.025,58.325 150.025,62.35 TP4.1@152.35,64.675
NetTP5_1: TP5.1 U5.28 | length 8
  Bottom Layer w0.1: U5.28@147.861,58.485 148.935,58.485 149.425,58.975 149.425,63.425 TP5.1@150.675,64.675
NJTRST: R39.2 U15.B5 | length 93.3
  Top Layer w0.1: R39.2@14.65,47.1 v1(15.425,47.1)
  Signal Layer 2 w0.1: v1(15.425,47.1) 19.225,47.1 20.925,48.8 41.8,48.8 42.2,48.4 46.45,48.4 48.525,46.325 v1(49.85,46.325) ; v1(87.925,38.473) 88.315,38.863 88.315,45.509 90.025,47.219 v1(90.025,47.875)
  Bottom Layer w0.1: v1(49.85,46.325) 50.15,46.625 88.775,46.625 v1(90.025,47.875) ; U15.B5@86.975,33.598 87.275,33.898 87.275,35.048 87.367,35.141 87.367,37.916 v1(87.925,38.473)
